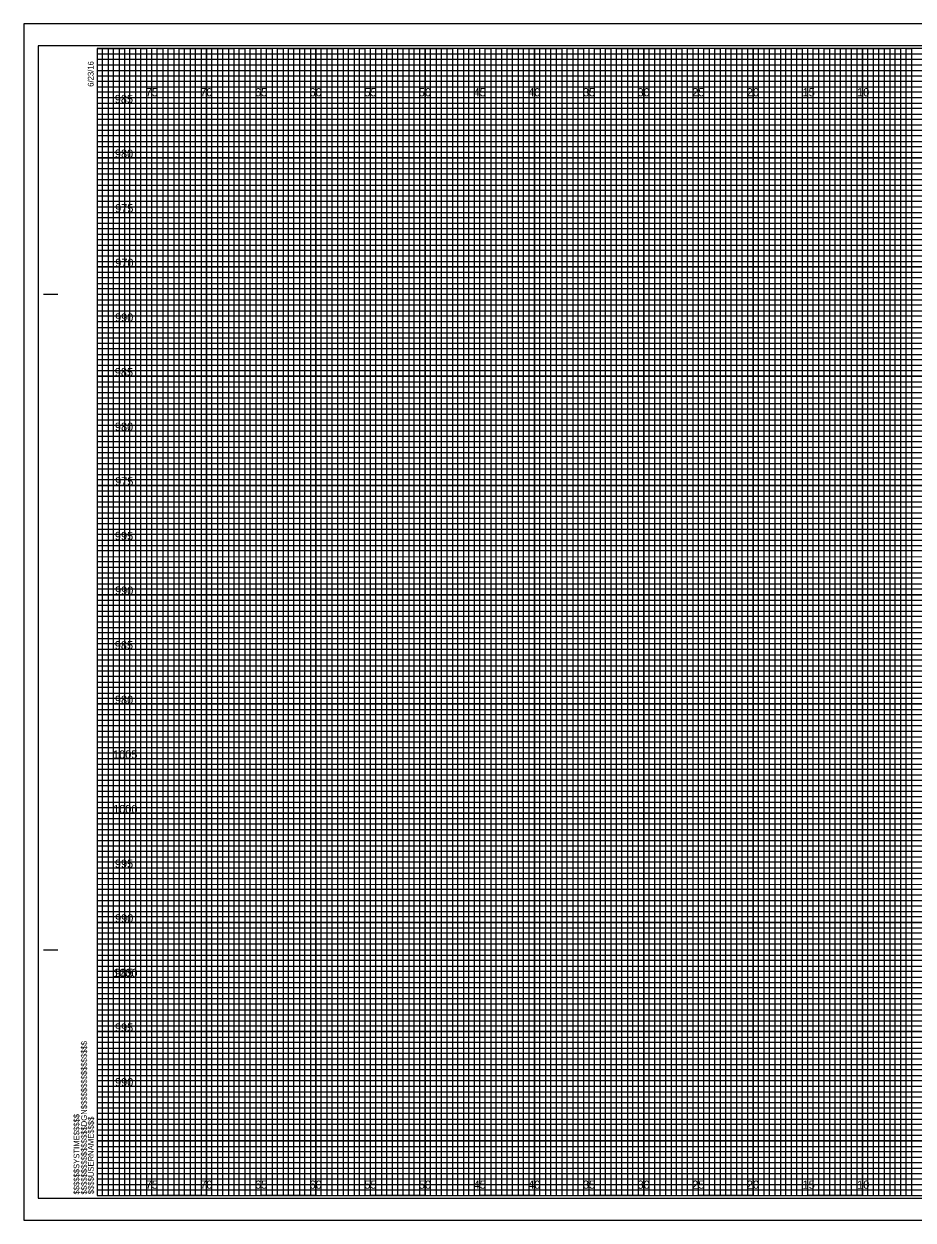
# Model space of a CAD drawing. Extents: x -7 to 162, y -2 to 107.
# Drawn here: x -6.7 to 74.6, y -2.3 to 107.3 of the extents above; entities that cross this region are included whole.
import ezdxf

# ---------------------------------------------------------------- set-up
doc = ezdxf.new("R2010")
doc.units = 0
for name, color, linetype in [('Prop XS Elevation Labels', 7, 'Continuous'), ('Prop XS Offset Labels', 7, 'Continuous'), ('Sheet Cross Section CELL', 7, 'Continuous'), ('Sheet Cross Section Grid Major CELL', 7, 'Continuous'), ('Sheet Cross Section Grid Middle CELL', 7, 'Continuous'), ('Sheet Cross Section Grid Minor 1 CELL', 7, 'Continuous'), ('Sheet Cross Section Grid Minor 2 CELL', 7, 'Continuous'), ('Sheet Cutting Line CELL', 7, 'Continuous'), ('Sheet DOT Grid CELL', 7, 'Continuous'), ('Sheet Plot Border Inside CELL', 7, 'Continuous'), ('Sheet Plot Border Outside CELL', 7, 'Continuous')]:
    doc.layers.add(name, color=color, linetype=linetype)

msp = doc.modelspace()

# ---------------------------------------------------------------- linework, layer by layer
at = {"layer": 'Sheet Cross Section CELL'}
for p, q in [((-4.9, 82.5), (-3.65, 82.5)), ((-4.85, 82.5), (-3.6, 82.5)), ((-4.9, 22.5), (-3.65, 22.5)), ((-4.85, 22.5), (-3.6, 22.5)), ((0, 0), (0, 0)), ((0, 0), (0, 0)), ((0, 0), (0, 0)), ((0, 0), (0, 0)), ((0, 0), (0, 0)), ((0, 0), (0, 0)), ((0, 0), (0, 0))]:
    msp.add_line(p, q, dxfattribs=at)
msp.add_lwpolyline([(160, 105), (0, 105), (0, 0), (160, 0)], close=True, dxfattribs=at)
at = {"layer": 'Sheet Cross Section Grid Major CELL'}
for p, q in [((5, 105), (0, 105)), ((5, 0), (5, 105)), ((15, 105), (10, 105)), ((10, 105), (10, 0)), ((15, 0), (15, 105)), ((25, 105), (20, 105)), ((20, 105), (20, 0)), ((25, 0), (25, 105)), ((35, 105), (30, 105)), ((30, 105), (30, 0)), ((35, 0), (35, 105)), ((45, 105), (40, 105)), ((40, 105), (40, 0)), ((45, 0), (45, 105)), ((55, 105), (50, 105)), ((50, 105), (50, 0)), ((55, 0), (55, 105)), ((65, 105), (60, 105)), ((60, 105), (60, 0)), ((65, 0), (65, 105)), ((75, 105), (70, 105)), ((70, 105), (70, 0)), ((10, 0), (5, 0)), ((20, 0), (15, 0)), ((30, 0), (25, 0)), ((40, 0), (35, 0)), ((50, 0), (45, 0)), ((60, 0), (55, 0)), ((70, 0), (65, 0))]:
    msp.add_line(p, q, dxfattribs=at)
for points in [[(0, 100), (160, 100), (160, 95), (0, 95)], [(0, 90), (160, 90), (160, 85), (0, 85)], [(0, 80), (160, 80), (160, 75), (0, 75)], [(0, 70), (160, 70), (160, 65), (0, 65)], [(0, 60), (160, 60), (160, 55), (0, 55)], [(0, 50), (160, 50), (160, 45), (0, 45)], [(0, 40), (160, 40), (160, 35), (0, 35)], [(0, 30), (160, 30), (160, 25), (0, 25)], [(0, 20), (160, 20), (160, 15), (0, 15)], [(0, 10), (160, 10), (160, 5), (0, 5)]]:
    msp.add_lwpolyline(points, dxfattribs=at)
at = {"layer": 'Sheet Cross Section Grid Middle CELL'}
for points in [[(0, 105), (2.5, 105), (2.5, 0), (7.5, 0), (7.5, 105), (12.5, 105), (12.5, 0), (17.5, 0), (17.5, 105), (22.5, 105), (22.5, 0), (27.5, 0), (27.5, 105), (32.5, 105), (32.5, 0), (37.5, 0), (37.5, 105), (42.5, 105), (42.5, 0), (47.5, 0), (47.5, 105), (52.5, 105), (52.5, 0), (57.5, 0), (57.5, 105), (62.5, 105), (62.5, 0), (67.5, 0), (67.5, 105), (72.5, 105), (72.5, 0), (77.5, 0)], [(0, 102.5), (137.5, 102.5)], [(0, 92.5), (160, 92.5), (160, 97.5), (0, 97.5)], [(0, 82.5), (160, 82.5), (160, 87.5), (0, 87.5)], [(0, 72.5), (160, 72.5), (160, 77.5), (0, 77.5)], [(0, 62.5), (160, 62.5), (160, 67.5), (0, 67.5)], [(0, 52.5), (160, 52.5), (160, 57.5), (0, 57.5)], [(0, 42.5), (160, 42.5), (160, 47.5), (0, 47.5)], [(0, 32.5), (160, 32.5), (160, 37.5), (0, 37.5)], [(0, 22.5), (160, 22.5), (160, 27.5), (0, 27.5)], [(0, 12.5), (160, 12.5), (160, 17.5), (0, 17.5)], [(0, 2.5), (160, 2.5), (160, 7.5), (0, 7.5)]]:
    msp.add_lwpolyline(points, dxfattribs=at)
at = {"layer": 'Sheet Cross Section Grid Minor 1 CELL'}
for p, q in [((0, 104.5), (130, 104.5)), ((130, 103.99), (0, 103.99)), ((0, 103.99), (0, 103.5)), ((0, 103.5), (130, 103.5)), ((130, 102.95), (0, 102.95)), ((0, 102.95), (0, 102)), ((0, 102), (160, 102))]:
    msp.add_line(p, q, dxfattribs=at)
for points in [[(0, 101.5), (135, 101.5), (160, 101.5), (160, 101), (0, 101)], [(0, 100.5), (160, 100.5), (160, 99.5), (0, 99.5)], [(0, 99), (160, 99), (160, 98.5), (0, 98.49)], [(0, 98), (160, 98), (160, 97), (0, 97)], [(0, 96.5), (160, 96.5), (160, 96), (0, 96)], [(0, 95.5), (160, 95.5), (160, 94.5), (0, 94.5)], [(0, 94), (160, 94), (160, 93.5), (0, 93.5)], [(0, 93), (160, 93), (160, 92), (0, 92)], [(0, 91.5), (160, 91.5), (160, 91), (0, 91)], [(0, 90.5), (160, 90.5), (160, 89.5), (0, 89.5)], [(0, 89), (160, 89), (160, 88.5), (0, 88.5)], [(0, 88), (160, 88), (160, 86.98), (160, 86.5), (160, 86), (0, 86)], [(0, 87), (160, 87), (160, 86.5), (0, 86.5)], [(0, 85.5), (160, 85.5), (160, 84.5), (0, 84.52)], [(0, 84.52), (160, 84.5), (160, 84), (0, 84)], [(0, 83.5), (160, 83.5), (160, 83), (0, 83)], [(0, 82), (160, 82), (160, 81.5), (0, 81.5)], [(0, 81), (160, 81), (160, 80.5), (0, 80.5)], [(-0.04, 79.45), (160, 79.45), (160, 78.94), (-0.04, 78.94)], [(0, 78.5), (160, 78.5), (160, 78), (0, 78)], [(0, 77), (160, 77), (160, 76.5), (0, 76.5)], [(0, 76), (160, 76), (160, 75.5), (0, 75.5)], [(0, 74.5), (160, 74.5), (160, 74), (0, 74)], [(0, 73.5), (160, 73.5), (160, 73), (0, 73)], [(0, 72), (160, 72), (160, 71.5), (0, 71.5)], [(0, 71), (160, 71), (160, 70.5), (0, 70.5)], [(0, 69.5), (160, 69.5), (160, 68.99), (0, 69)], [(0, 68.5), (160, 68.5), (160, 68), (0, 68)], [(0, 67), (160, 67), (160, 66.5), (0, 66.5)], [(0, 66), (160, 66), (160, 65.5), (0, 65.5)], [(0, 64.5), (160, 64.5), (160, 64), (0, 64)], [(0, 63.5), (160, 63.5), (160, 63), (0, 63)], [(0, 62), (160, 62), (160, 61.5), (0, 61.5)], [(0, 61), (160, 61), (160, 60.5), (0, 60.5)], [(0, 59.5), (160, 59.5), (160, 59), (0, 59)], [(0, 58.5), (160.03, 58.45), (160, 58), (0, 58)], [(0, 57), (160, 57), (160, 56.5), (0, 56.5)], [(0, 56), (160, 56), (160, 55.5), (0, 55.5)], [(0, 54.5), (160, 54.5), (160, 54), (0, 54)], [(0, 53.5), (160, 53.5), (160, 53), (0, 53)], [(0, 52), (160, 52), (160, 51.5), (0, 51.5)], [(0, 51), (160, 51), (160, 50.5), (0, 50.5)], [(0, 49.5), (160, 49.5), (160, 49), (0, 49)], [(0, 48.5), (160, 48.5), (160, 48), (0, 48)], [(0, 47), (160, 47), (160, 46.5), (0, 46.5)], [(0, 46), (160, 46), (160, 45.5), (0, 45.5)], [(0, 44.5), (160, 44.5), (160, 44), (0, 44)], [(0, 43.5), (160, 43.5), (160, 43), (0, 43)], [(0, 42), (160, 42), (160, 41.5), (0, 41.5)], [(0, 41), (160, 41), (160, 40.5), (0, 40.5)], [(0, 39.5), (160, 39.5), (160, 38.99), (0, 39)], [(0, 38.5), (160, 38.5), (160, 38), (0, 38)], [(0, 37), (160, 37), (160, 36.5), (0, 36.5)], [(0, 36), (160, 36), (160, 35.5), (0, 35.5)], [(0, 34.5), (160, 34.5), (160, 34), (0, 34)], [(0, 33.5), (160, 33.5), (160, 33), (0, 33)], [(0, 32), (160, 32), (160, 31.5), (0, 31.5)], [(0, 31), (160, 31), (160, 30.5), (0, 30.5)], [(0, 29.5), (160, 29.5), (160, 29), (0, 29)], [(0, 28.5), (160.03, 28.46), (160, 28), (0, 28)], [(0, 27), (160, 27), (160, 26.5), (0, 26.5)], [(0, 26), (160, 26), (160, 25.5), (0, 25.5)], [(0, 24.5), (160, 24.5), (160, 24), (0, 24)], [(0, 23.5), (160, 23.5), (160, 23), (0, 23)], [(0, 22), (160, 22), (160, 21.5), (0, 21.5)], [(0, 21), (160, 21), (160, 20.5), (0, 20.5)], [(0, 19.5), (160, 19.5), (160, 19), (0, 19)], [(0, 18.5), (160, 18.5), (160, 18), (0, 18)], [(0, 17), (160, 17), (160, 16.5), (0, 16.5)], [(0, 16), (160, 16), (160, 15.5), (0, 15.5)], [(0, 14.5), (160, 14.5), (160, 14), (0, 14)], [(0, 13.5), (160, 13.5), (160, 13), (0, 13)], [(0, 12), (160, 12), (160, 11.5), (0, 11.5)], [(0, 11), (160, 11), (160, 10.5), (0, 10.5)], [(0, 9.5), (160, 9.5), (160, 9), (0, 9)], [(0, 8.5), (160, 8.5), (160, 8), (0, 8)], [(0, 7), (160, 7), (160, 6.5), (0, 6.5)], [(0, 6), (160, 6), (160, 5.5), (0, 5.5)], [(0, 4.5), (160, 4.5), (160, 4), (0, 4)], [(0, 3.5), (160, 3.5), (160, 3), (0, 3)], [(0, 2), (160, 2), (160, 1.5), (0, 1.5)], [(0, 1), (160, 1), (160, 0.5), (0, 0.5)]]:
    msp.add_lwpolyline(points, dxfattribs=at)
at = {"layer": 'Sheet Cross Section Grid Minor 2 CELL'}
for points in [[(0, 0), (0.5, 0), (0.5, 105), (1, 105), (1, 0)], [(1, 0), (1.5, 0), (1.5, 105), (2, 105), (2, 0)], [(2.5, 0), (3, 0), (3, 105), (3.5, 105), (3.5, 0)], [(3.5, 0), (4, 0), (4, 105), (4.5, 105), (4.5, 0)], [(5, 0), (5.5, 0), (5.5, 105), (6, 105), (6, 0)], [(6, 0), (6.5, 0), (6.5, 105), (7, 105), (7, 0)], [(7.5, 0), (8, 0), (8, 105), (8.5, 105), (8.5, 0)], [(8.5, 0), (9, 0), (9, 105), (9.5, 105), (9.5, 0)], [(10, 0), (10.5, 0), (10.5, 105), (11, 105), (11, 0)], [(11, 0), (11.5, 0), (11.5, 105), (12, 105), (12, 0)], [(12.5, 0), (13, 0), (13, 105), (13.5, 105), (13.5, 0)], [(13.5, 0), (14, 0), (14, 105), (14.5, 105), (14.5, 0)], [(15, 0), (15.5, 0), (15.5, 105), (16, 105), (16, 0)], [(16, 0), (16.5, 0), (16.5, 105), (17, 105), (17, 0)], [(17.5, 0), (18, 0), (18, 105), (18.5, 105), (18.5, 0)], [(18.5, 0), (19, 0), (19, 105), (19.5, 105), (19.5, 0)], [(20, 0), (20.5, 0), (20.5, 105), (21, 105), (21, 0)], [(21, 0), (21.5, 0), (21.5, 105), (22, 105), (22, 0)], [(22.5, 0), (23, 0), (23, 105), (23.5, 105), (23.5, 0)], [(23.5, 0), (24, 0), (24, 105), (24.5, 105), (24.5, 0)], [(25, 0), (25.5, 0), (25.5, 105), (26, 105), (26, 0)], [(26, 0), (26.5, 0), (26.5, 105), (27, 105), (27, 0)], [(27.5, 0), (28, 0), (28, 105), (28.5, 105), (28.5, 0)], [(28.5, 0), (29, 0), (29, 105), (29.5, 105), (29.5, 0)], [(30, 0), (30.5, 0), (30.5, 105), (31, 105), (31, 0)], [(31, 0), (31.5, 0), (31.5, 105), (32, 105), (32, 0)], [(32.5, 0), (33, 0), (33, 105), (33.5, 105), (33.5, 0)], [(33.5, 0), (34, 0), (34, 105), (34.5, 105), (34.5, 0)], [(35, 0), (35.5, 0), (35.5, 105), (36, 105), (36, 0)], [(36, 0), (36.5, 0), (36.5, 105), (37, 105), (37, 0)], [(37.5, 0), (38, 0), (38, 105), (38.5, 105), (38.5, 0)], [(38.5, 0), (39, 0), (39, 105), (39.5, 105), (39.5, 0)], [(40, 0), (40.5, 0), (40.5, 105), (41, 105), (41, 0)], [(41, 0), (41.5, 0), (41.5, 105), (42, 105), (42, 0)], [(42.5, 0), (43, 0), (43, 105), (43.5, 105), (43.5, 0)], [(43.5, 0), (44, 0), (44, 105), (44.5, 105), (44.5, 0)], [(45, 0), (45.5, 0), (45.5, 105), (46, 105), (46, 0)], [(46, 0), (46.5, 0), (46.5, 105), (47, 105), (47, 0)], [(47.5, 0), (48, 0), (48, 105), (48.5, 105), (48.5, 0)], [(48.5, 0), (49, 0), (49, 105), (49.5, 105), (49.5, 0)], [(50, 0), (50.5, 0), (50.5, 105), (51, 105), (51, 0)], [(51, 0), (51.5, 0), (51.5, 105), (52, 105), (52, 0)], [(52.5, 0), (53, 0), (53, 105), (53.5, 105), (53.5, 0)], [(53.5, 0), (54, 0), (54, 105), (54.5, 105), (54.5, 0)], [(55, 0), (55.5, 0), (55.5, 105), (56, 105), (56, 0)], [(56, 0), (56.5, 0), (56.5, 105), (57, 105), (57, 0)], [(57.5, 0), (58, 0), (58, 105), (58.5, 105), (58.5, 0)], [(58.5, 0), (59, 0), (59, 105), (59.5, 105), (59.5, 0)], [(60, 0), (60.5, 0), (60.5, 105), (61, 105), (61, 0)], [(61, 0), (61.5, 0), (61.5, 105), (62, 105), (62, 0)], [(62.5, 0), (63, 0), (63, 105), (63.5, 105), (63.5, 0)], [(63.5, 0), (64, 0), (64, 105), (64.5, 105), (64.5, 0)], [(65, 0), (65.5, 0), (65.5, 105), (66, 105), (66, 0)], [(66, 0), (66.5, 0), (66.5, 105), (67, 105), (67, 0)], [(67.5, 0), (68, 0), (68, 105), (68.5, 105), (68.5, 0)], [(68.5, 0), (69, 0), (69, 105), (69.5, 105), (69.5, 0)], [(70, 0), (70.5, 0), (70.5, 105), (71, 105), (71, 0)], [(71, 0), (71.5, 0), (71.5, 105), (72, 105), (72, 0)], [(72.5, 0), (73, 0), (73, 105), (73.5, 105), (73.5, 0)], [(73.5, 0), (74, 0), (74, 105), (74.5, 105), (74.5, 0)]]:
    msp.add_lwpolyline(points, dxfattribs=at)
at = {"layer": 'Sheet Cutting Line CELL'}
for p, q in [((161.65, 107.25), (-6.7, 107.25)), ((-6.7, 107.25), (-6.7, -2.25)), ((-6.7, -2.25), (161.65, -2.25))]:
    msp.add_line(p, q, dxfattribs=at)
at = {"layer": 'Sheet DOT Grid CELL'}
for p, q in [((5, 0), (5, 105)), ((10, 0), (10, 105)), ((15, 0), (15, 105)), ((20, 0), (20, 105)), ((25, 0), (25, 105)), ((30, 0), (30, 105)), ((35, 0), (35, 105)), ((40, 0), (40, 105)), ((45, 0), (45, 105)), ((50, 0), (50, 105)), ((55, 0), (55, 105)), ((60, 0), (60, 105)), ((65, 0), (65, 105)), ((70, 0), (70, 105)), ((0, 100), (160, 100)), ((0, 95), (160, 95)), ((0, 90), (160, 90)), ((0, 85), (160, 85)), ((0, 80), (160, 80)), ((0, 75), (160, 75)), ((0, 70), (160, 70)), ((0, 65), (160, 65)), ((0, 60), (160, 60)), ((0, 55), (160, 55)), ((0, 50), (160, 50)), ((0, 45), (160, 45)), ((0, 40), (160, 40)), ((0, 35), (160, 35)), ((0, 30), (160, 30)), ((0, 25), (160, 25)), ((0, 20), (160, 20)), ((0, 15), (160, 15)), ((0, 10), (160, 10)), ((0, 5), (160, 5))]:
    msp.add_line(p, q, dxfattribs=at)
at = {"layer": 'Sheet Plot Border Inside CELL'}
msp.add_lwpolyline([(-5.4, -0.25), (161.2, -0.25), (161.2, 105.25), (-5.4, 105.25)], close=True, dxfattribs=at)
at = {"layer": 'Sheet Plot Border Outside CELL'}
msp.add_lwpolyline([(-6.7, -2.25), (161.65, -2.25), (161.65, 107.25), (-6.7, 107.25)], close=True, dxfattribs=at)

# ---------------------------------------------------------------- texts
at = {"layer": 'Prop XS Elevation Labels'}
for s, p in [('985', (1.61, 100)), ('980', (1.62, 95)), ('975', (1.64, 90)), ('970', (1.65, 85)), ('990', (1.63, 80)), ('985', (1.61, 75)), ('980', (1.62, 70)), ('975', (1.64, 65)), ('995', (1.62, 60)), ('990', (1.63, 55)), ('985', (1.61, 50)), ('980', (1.62, 45)), ('1005', (1.45, 40)), ('1000', (1.46, 35)), ('995', (1.62, 30)), ('990', (1.63, 25)), ('1000', (1.46, 20)), ('985', (1.61, 20)), ('995', (1.62, 15)), ('990', (1.63, 10))]:
    msp.add_text(s, height=0.75, dxfattribs=at).set_placement(p)
at = {"layer": 'Prop XS Offset Labels'}
for s, p in [('75', (4.44, 100.62)), ('70', (9.43, 100.62)), ('65', (14.44, 100.62)), ('60', (19.43, 100.62)), ('55', (24.44, 100.62)), ('50', (29.43, 100.62)), ('45', (34.44, 100.62)), ('40', (39.43, 100.62)), ('35', (44.44, 100.62)), ('30', (49.43, 100.62)), ('25', (54.44, 100.62)), ('20', (59.43, 100.62)), ('15', (64.53, 100.62)), ('10', (69.52, 100.62)), ('75', (4.44, 0.62)), ('70', (9.43, 0.62)), ('65', (14.44, 0.62)), ('60', (19.43, 0.62)), ('55', (24.44, 0.62)), ('50', (29.43, 0.62)), ('45', (34.44, 0.62)), ('40', (39.43, 0.62)), ('35', (44.44, 0.62)), ('30', (49.43, 0.62)), ('25', (54.44, 0.62)), ('20', (59.43, 0.62)), ('15', (64.53, 0.62)), ('10', (69.52, 0.62))]:
    msp.add_text(s, height=0.75, dxfattribs=at).set_placement(p)
at = {"layer": 'Sheet Cross Section CELL'}
for s, p in [('6/23/16', (-0.33, 101.5)), ('$$$$$$$$$$$$$$$$DGN$$$$$$$$$$$$$$$$', (-0.94, 0.09)), ('$$$$$$SYSTIME$$$$$', (-1.63, 0.09)), ('$$$$USERNAME$$$$', (-0.31, 0.12))]:
    msp.add_text(s, height=0.525, rotation=90, dxfattribs=at).set_placement(p)

doc.saveas('drawing.dxf')
